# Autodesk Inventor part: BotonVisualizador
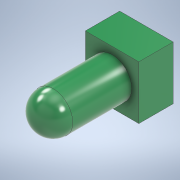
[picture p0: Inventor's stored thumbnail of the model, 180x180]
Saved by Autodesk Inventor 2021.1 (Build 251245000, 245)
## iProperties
Created: 2021-06
Part Number: BotonVisualizador
Material: Genérico
Document SubType Name: Modeling
Designer: Ricardo
Density: 1 g/cm^3
Appearance: Valor por defecto
Author: Ricardo
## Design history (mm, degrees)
sketch "Boceto1"
  geometry: L1 (-1.5, -1.5)-(1.5, -1.5); L2 (1.5, -1.5)-(1.5, 1.5); L3 (1.5, 1.5)-(-1.5, 1.5); L4 (-1.5, 1.5)-(-1.5, -1.5); L5 (-1.5, -1.5)-(1.5, 1.5); L6 (1.5, -1.5)-(-1.5, 1.5); L7 (-4.25, -4.25)-(4.25, -4.25); L8 (4.25, -4.25)-(4.25, 4.25); L9 (4.25, 4.25)-(-4.25, 4.25); L10 (-4.25, 4.25)-(-4.25, -4.25); L11 (-4.25, -4.25)-(4.25, 4.25); L12 (4.25, -4.25)-(-4.25, 4.25); L13 (-5.45, 5.45)-(5.45, 5.45); L14 (5.45, 5.45)-(5.45, -5.45); L15 (5.45, -5.45)-(-5.45, -5.45); L16 (-5.45, -5.45)-(-5.45, 5.45); 1 further point
  constraints: 32 end point, 6 parallel, 4 midpoint, 3 perpendicular, 2 horizontal, 3 other
  dimensions: "d0" = 3 distance of L3.end L2.end; "d1" = 3 distance of L2.end L1.end; "d2" = 8.5 distance of L9.end L8.end; "d3" = 8.5 distance of L8.end L7.end; "d4" = 1.2 distance between parallel lines of L9 L13
extrude "Extrusión1" new body sketch "Boceto1" distance "d5" = 5; taper "d6" = 0 deg
extrude "Extrusión2" join sketch "Boceto1" distance "d7" = 2; taper "d8" = 0 deg
node "Superficie envolvente"
node "Plano de trabajo2"
sketch "Boceto2"
  geometry: L1 (-1.5, -1.5)-(1.5, -1.5) reference; L2 (-1.5, 1.5)-(-1.5, -1.5) reference; L3 (1.5, 1.5)-(-1.5, 1.5) reference; L4 (1.5, -1.5)-(1.5, 1.5) reference; C1 r 4 at (0, 0); 1 further point
  constraints: 1 centre point, 1 coincident
  dimensions: "d11" = 8 diameter of C1
sketch "Boceto5"
  geometry: L1 (-1.5, 1.5)-(1.5, 1.5) reference; L2 (-1.5, -1.5)-(-1.5, 1.5) reference; L3 (1.5, -1.5)-(-1.5, -1.5) reference; L4 (1.5, 1.5)-(1.5, -1.5) reference; C1 r 4 at (0, 0); 1 further point
  constraints: 1 centre point, 1 coincident
  dimensions: "d23" = 8 diameter of C1
extrude "Extrusión5" join sketch "Boceto5" distance "d24" = 12; taper "d25" = 0 deg
sketch "Boceto6"
  geometry: L1 (0, 4)-(0, -4); L2 (0, 4.576)-(0, -4.999); A1 r 4 centre (0, 0) between (0, 4) and (0, -4) reference; 1 further point
  constraints: 4 end point, 2 point on circle, 1 point on line, 1 vertical
revolve "Revolución2" sketch "Boceto6" stored, may be unused: angle "d26" = 90 deg
node "Plano de trabajo5"
sketch "Boceto7"
  geometry: L1 (0, 8.6)-(0, -16.6) reference; 1 further point
node "Sólido1"
other parameters: "d9" = -15.75, "d10" = 0
